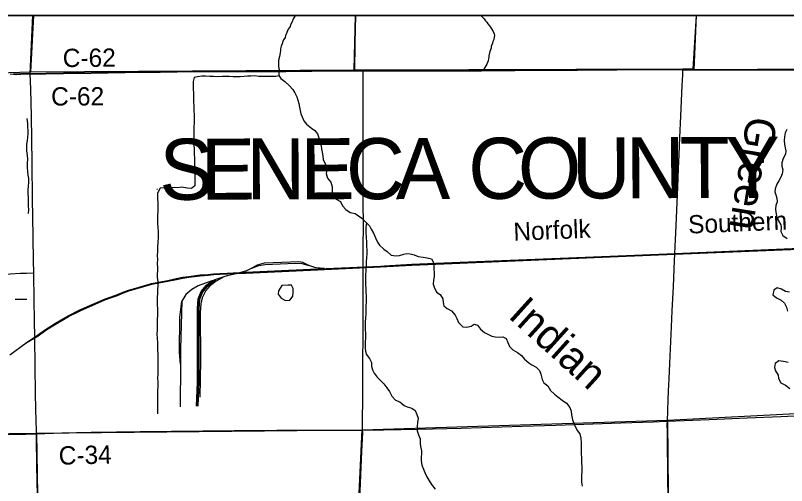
# Model space of a CAD drawing. Extents: x 0 to 34, y 0 to 22.
# Drawn here: x 5.242 to 6.439, y 20.17 to 20.9 of the extents above; entities that cross this region are included whole.
import ezdxf

# ---------------------------------------------------------------- set-up
doc = ezdxf.new("R2010")
doc.units = 0
for name, color, linetype in [('GM_X_Corporation', 7, 'Continuous'), ('GM_X_County_Road', 7, 'Continuous'), ('GM_X_County_Road_Text', 7, 'Continuous'), ('GM_X_County_Text', 7, 'Continuous'), ('GM_X_Minor_Lake', 7, 'Continuous'), ('GM_X_Minor_River', 7, 'Continuous'), ('GM_X_Minor_River_Text', 7, 'Continuous'), ('GM_X_Rail_Line', 7, 'Continuous'), ('GM_X_Rail_Line_Text', 7, 'Continuous'), ('GM_X_Township_Road', 7, 'Continuous'), ('SH_Data', 7, 'Continuous')]:
    doc.layers.add(name, color=color, linetype=linetype)

msp = doc.modelspace()

# ---------------------------------------------------------------- linework, layer by layer
at = {"layer": 'GM_X_Corporation'}
for points in [[(8.9, 20.9), (2.1, 20.9)], [(6.7997, 20.9), (3.8013, 20.9)], [(6.455, 20.8159), (6.4373, 20.816), (6.3938, 20.8159), (6.3543, 20.8158), (6.3344, 20.8158), (6.3036, 20.8158), (6.2954, 20.8159), (6.2828, 20.8161), (6.2781, 20.8161), (6.2682, 20.8162), (6.2104, 20.8162), (6.1757, 20.8159), (6.1145, 20.8155), (6.0613, 20.8151), (6.0172, 20.8146), (5.9656, 20.8142), (5.9482, 20.8141), (5.9187, 20.8141), (5.868, 20.8143), (5.8202, 20.8141), (5.7876, 20.8144), (5.7817, 20.8144), (5.7688, 20.8143), (5.759, 20.8143), (5.7018, 20.8138), (5.6617, 20.8133), (5.6085, 20.8132), (5.5485, 20.8132), (5.5196, 20.8132), (5.4665, 20.8122), (5.4121, 20.8115), (5.3592, 20.8108), (5.3384, 20.8104), (5.3164, 20.8102), (5.289, 20.8097), (5.2645, 20.8094), (5.2558, 20.8096), (5.2527, 20.8095), (5.2501, 20.8093), (5.2468, 20.809), (5.2444, 20.8088), (5.2425, 20.8087), (5.239, 20.8089)], [(5.239, 20.8089), (5.2425, 20.8087), (5.2444, 20.8088), (5.2468, 20.809), (5.2501, 20.8093), (5.2527, 20.8095), (5.2558, 20.8096), (5.2645, 20.8094), (5.289, 20.8097), (5.3164, 20.8102), (5.3384, 20.8104), (5.3592, 20.8108), (5.4121, 20.8115), (5.4665, 20.8122), (5.5196, 20.8132), (5.5485, 20.8132), (5.6085, 20.8132), (5.6617, 20.8133), (5.7018, 20.8138), (5.759, 20.8143), (5.7688, 20.8143), (5.7817, 20.8144), (5.7876, 20.8144), (5.8202, 20.8141), (5.868, 20.8143), (5.9187, 20.8141), (5.9482, 20.8141), (5.9656, 20.8142), (6.0172, 20.8146), (6.0613, 20.8151), (6.1145, 20.8155), (6.1757, 20.8159), (6.2104, 20.8162), (6.2682, 20.8162), (6.2781, 20.8161), (6.2828, 20.8161), (6.2954, 20.8159), (6.3036, 20.8158), (6.3344, 20.8158), (6.3543, 20.8158), (6.3938, 20.8159), (6.4373, 20.816), (6.455, 20.8159)], [(5.239, 20.8089), (5.2425, 20.8087), (5.2444, 20.8088), (5.2468, 20.809), (5.2501, 20.8093), (5.2527, 20.8095), (5.2558, 20.8096), (5.2645, 20.8094), (5.289, 20.8097), (5.3164, 20.8102), (5.3384, 20.8104), (5.3592, 20.8108), (5.4121, 20.8115), (5.4665, 20.8122), (5.5196, 20.8132), (5.5485, 20.8132), (5.6085, 20.8132), (5.6617, 20.8133), (5.7018, 20.8138), (5.759, 20.8143), (5.7688, 20.8143), (5.7817, 20.8144), (5.7876, 20.8144), (5.8202, 20.8141), (5.868, 20.8143), (5.9187, 20.8141), (5.9482, 20.8141), (5.9656, 20.8142), (6.0172, 20.8146), (6.0613, 20.8151), (6.1145, 20.8155), (6.1757, 20.8159), (6.2104, 20.8162), (6.2682, 20.8162), (6.2781, 20.8161), (6.2828, 20.8161), (6.2954, 20.8159), (6.3036, 20.8158), (6.3344, 20.8158), (6.3543, 20.8158), (6.3938, 20.8159), (6.4373, 20.816), (6.455, 20.8159)], [(5.239, 20.8089), (5.2425, 20.8087), (5.2444, 20.8088), (5.2468, 20.809), (5.2501, 20.8093), (5.2527, 20.8095), (5.2558, 20.8096), (5.2645, 20.8094), (5.289, 20.8097), (5.3164, 20.8102), (5.3384, 20.8104), (5.3592, 20.8108), (5.4121, 20.8115), (5.4665, 20.8122), (5.5196, 20.8132), (5.5485, 20.8132), (5.6085, 20.8132), (5.6617, 20.8133), (5.7018, 20.8138), (5.759, 20.8143), (5.7688, 20.8143), (5.7817, 20.8144), (5.7876, 20.8144), (5.8202, 20.8141), (5.868, 20.8143), (5.9187, 20.8141), (5.9482, 20.8141), (5.9656, 20.8142), (6.0172, 20.8146), (6.0613, 20.8151), (6.1145, 20.8155), (6.1757, 20.8159), (6.2104, 20.8162), (6.2682, 20.8162), (6.2781, 20.8161), (6.2828, 20.8161), (6.2954, 20.8159), (6.3036, 20.8158), (6.3344, 20.8158), (6.3543, 20.8158), (6.3938, 20.8159), (6.4373, 20.816), (6.455, 20.8159)]]:
    msp.add_lwpolyline(points, dxfattribs=at)
for points in [[(5.2699, 20.9), (4.8122, 20.9), (4.8145, 20.7984), (5.265, 20.8123)], [(5.7697, 20.9), (5.2699, 20.9), (5.265, 20.8123), (5.7676, 20.8153)], [(6.299, 20.9), (5.7697, 20.9), (5.7676, 20.8153), (5.7804, 20.8154), (6.2773, 20.817), (6.2943, 20.817)], [(6.254, 20.2716), (6.7719, 20.2989), (6.7597, 19.805), (6.7595, 19.7972), (6.2587, 19.7668)], [(5.7802, 20.2569), (6.254, 20.2716), (6.2587, 19.7668), (5.7563, 19.7534)], [(5.2745, 20.2518), (5.2825, 19.7741), (5.2855, 19.7694), (5.2893, 19.764), (5.2986, 19.7516), (5.3057, 19.7445), (5.3092, 19.7364), (4.8186, 19.7484), (4.8123, 20.246)], [(5.2745, 20.2518), (5.7802, 20.2569), (5.7563, 19.7534), (5.2986, 19.7516), (5.2893, 19.764), (5.2855, 19.7694), (5.2825, 19.7741)]]:
    msp.add_lwpolyline(points, close=True, dxfattribs=at)
at = {"layer": 'GM_X_County_Road'}
for p, q in [((5.2646, 20.8092), (5.2691, 20.9)), ((6.2955, 20.8157), (6.2992, 20.9)), ((5.7689, 20.8141), (5.7818, 20.8141))]:
    msp.add_line(p, q, dxfattribs=at)
for points in [[(5.2646, 20.8092), (5.2891, 20.8094), (5.3165, 20.8099), (5.3385, 20.8102), (5.3594, 20.8105), (5.4122, 20.8112), (5.4666, 20.8119), (5.5197, 20.8129), (5.5486, 20.8129), (5.6086, 20.8129), (5.6618, 20.8131), (5.7019, 20.8136), (5.7591, 20.8141), (5.7689, 20.8141)], [(5.2704, 20.5006), (5.2701, 20.5197), (5.2695, 20.5555), (5.269, 20.5881), (5.2686, 20.6145), (5.2679, 20.6714), (5.2673, 20.7078), (5.2667, 20.7438), (5.2656, 20.7855), (5.2646, 20.8092)], [(5.7818, 20.8141), (5.7877, 20.8141), (5.8203, 20.8139), (5.8681, 20.814), (5.9188, 20.8138), (5.9483, 20.8138), (5.9657, 20.8139), (6.0173, 20.8143), (6.0614, 20.8148), (6.1146, 20.8152), (6.1758, 20.8157), (6.2105, 20.8159), (6.2683, 20.8159), (6.2782, 20.8158)], [(6.2782, 20.8158), (6.2829, 20.8158), (6.2955, 20.8157)], [(6.2955, 20.8157), (6.3038, 20.8155), (6.3345, 20.8155), (6.3544, 20.8156), (6.3939, 20.8156), (6.4374, 20.8157), (6.4551, 20.8156), (6.498, 20.8156), (6.5114, 20.8156), (6.5375, 20.8155)], [(5.2744, 20.2508), (5.2744, 20.2553), (5.2737, 20.2882), (5.2732, 20.314), (5.2725, 20.3544), (5.2718, 20.401), (5.2713, 20.4253), (5.271, 20.4595), (5.2705, 20.4977), (5.2704, 20.5006)], [(6.2541, 20.2703), (6.3187, 20.2728), (6.378, 20.2752), (6.4302, 20.2774), (6.4857, 20.2799), (6.5197, 20.2816)], [(5.7809, 20.2564), (5.8138, 20.2567), (5.8673, 20.2578), (5.9341, 20.2595), (6.0286, 20.2624), (6.0811, 20.2642), (6.1817, 20.2676), (6.2327, 20.2693), (6.2513, 20.2702), (6.2541, 20.2703)], [(5.1981, 20.2489), (5.2578, 20.2502), (5.2699, 20.2506), (5.2744, 20.2508)], [(5.2744, 20.2508), (5.3138, 20.252), (5.3595, 20.253), (5.399, 20.2538), (5.4356, 20.2544), (5.4844, 20.2548), (5.5814, 20.2557), (5.6479, 20.2562), (5.7166, 20.2564), (5.7601, 20.2564), (5.7809, 20.2564)], [(5.2798, 19.9976), (5.2798, 19.9993), (5.2795, 20.0104), (5.2787, 20.0381), (5.2772, 20.103), (5.2767, 20.1239), (5.276, 20.1546), (5.2756, 20.1782), (5.2752, 20.2012), (5.2751, 20.2127), (5.2747, 20.2314), (5.2745, 20.2457), (5.2744, 20.2508)]]:
    msp.add_lwpolyline(points, dxfattribs=at)
at = {"layer": 'GM_X_Minor_Lake'}
for points in [[(5.6554, 20.481), (5.6501, 20.4723), (5.6498, 20.4674), (5.6543, 20.4609), (5.6611, 20.4575), (5.6678, 20.4582), (5.6698, 20.4607)], [(5.6698, 20.4607), (5.6727, 20.4642), (5.6729, 20.4692), (5.673, 20.476), (5.6703, 20.4811), (5.6652, 20.4814), (5.6554, 20.481)]]:
    msp.add_lwpolyline(points, dxfattribs=at)
at = {"layer": 'GM_X_Minor_River'}
msp.add_line((5.4624, 20.6297), (5.4615, 20.6299), dxfattribs=at)
for points in [[(5.6766, 20.9), (5.6754, 20.8986), (5.6739, 20.8963), (5.6727, 20.8939), (5.6718, 20.8916), (5.6708, 20.8891), (5.6689, 20.8856), (5.6682, 20.8827), (5.6655, 20.8786), (5.6644, 20.8763), (5.6632, 20.8737), (5.662, 20.8708), (5.6611, 20.8686), (5.6605, 20.8659), (5.6582, 20.8623), (5.657, 20.8595), (5.6558, 20.8559), (5.6544, 20.8521), (5.6536, 20.8481), (5.6534, 20.8457), (5.6528, 20.8424), (5.6524, 20.839), (5.652, 20.836), (5.651, 20.8326), (5.6504, 20.8292), (5.6503, 20.8258), (5.6501, 20.8212), (5.6506, 20.8174), (5.6521, 20.8131)], [(5.9654, 20.9), (5.9656, 20.8991), (5.9694, 20.8947), (5.9716, 20.8918), (5.9739, 20.8895), (5.9755, 20.887), (5.9778, 20.884), (5.9793, 20.8817), (5.9811, 20.879), (5.9838, 20.875), (5.9852, 20.8715), (5.9858, 20.8691), (5.9852, 20.866), (5.9844, 20.8628), (5.9832, 20.8596), (5.9824, 20.857), (5.9816, 20.8541), (5.9806, 20.8519), (5.9802, 20.8492), (5.9794, 20.8464), (5.9785, 20.8441), (5.9767, 20.8373), (5.9767, 20.835), (5.9764, 20.8327), (5.9757, 20.8295), (5.9749, 20.8269), (5.9737, 20.8244), (5.9676, 20.8142)], [(5.6509, 20.813), (5.651, 20.8069), (5.6538, 20.8021), (5.66, 20.7972), (5.6672, 20.7909), (5.6726, 20.7848), (5.6756, 20.7798), (5.6788, 20.7734), (5.6805, 20.7686), (5.6817, 20.7633), (5.6827, 20.7578), (5.684, 20.7525), (5.6852, 20.7473), (5.6869, 20.7426), (5.6897, 20.7365), (5.6935, 20.7314), (5.7014, 20.7252), (5.7067, 20.7216), (5.7106, 20.7161), (5.7128, 20.71), (5.7147, 20.7047), (5.7165, 20.6977), (5.7173, 20.6927), (5.7182, 20.6876), (5.7191, 20.6819), (5.7196, 20.6766), (5.722, 20.6709), (5.7247, 20.6659), (5.7254, 20.661), (5.7242, 20.6546), (5.7261, 20.6473), (5.7313, 20.6411), (5.7334, 20.6338), (5.7335, 20.6261), (5.7344, 20.6213), (5.7397, 20.6146), (5.7463, 20.611), (5.7496, 20.6047), (5.7547, 20.5988), (5.7615, 20.5942), (5.7692, 20.5927), (5.7796, 20.5852)], [(5.6513, 20.8064), (5.6461, 20.8054), (5.6394, 20.8051), (5.6328, 20.8053), (5.6267, 20.8052), (5.6199, 20.8054), (5.6129, 20.806), (5.6071, 20.8058), (5.602, 20.8057), (5.5968, 20.8051), (5.5906, 20.8048), (5.58, 20.8049), (5.5739, 20.8053), (5.5681, 20.8051), (5.5631, 20.8052), (5.556, 20.8048), (5.5495, 20.8052), (5.5435, 20.8051), (5.5372, 20.8057), (5.531, 20.8055), (5.5243, 20.8048), (5.5194, 20.8035), (5.5177, 20.7973), (5.5176, 20.7918), (5.518, 20.785), (5.5181, 20.7796), (5.5183, 20.7719), (5.5184, 20.7658), (5.5188, 20.7599), (5.5189, 20.7525), (5.5192, 20.7453), (5.5192, 20.7332), (5.5189, 20.7269), (5.5188, 20.7099), (5.5186, 20.7047), (5.5186, 20.6983), (5.5191, 20.6934), (5.5196, 20.686), (5.5197, 20.6767), (5.5199, 20.6713), (5.5199, 20.6657), (5.5202, 20.6592), (5.5202, 20.653), (5.5203, 20.6482), (5.5205, 20.6418), (5.5204, 20.6353), (5.5151, 20.6314), (5.5083, 20.632), (5.5003, 20.6332), (5.4937, 20.6323), (5.4884, 20.6329), (5.4818, 20.6323), (5.4735, 20.6322), (5.4668, 20.632), (5.4626, 20.6239), (5.4626, 20.6159), (5.4627, 20.6093), (5.4631, 20.6046), (5.4628, 20.5983), (5.4626, 20.5872)], [(5.2597, 20.7399), (5.2604, 20.7325), (5.2606, 20.7272), (5.2609, 20.7209), (5.261, 20.716), (5.2608, 20.7109), (5.26, 20.7057), (5.259, 20.7003), (5.259, 20.6946), (5.2591, 20.6898), (5.26, 20.6828), (5.2606, 20.6769), (5.2603, 20.6705), (5.2603, 20.664), (5.2606, 20.6579), (5.2613, 20.6522), (5.262, 20.6467), (5.2624, 20.6405), (5.2618, 20.6355), (5.2611, 20.6289), (5.2611, 20.6238), (5.2616, 20.6171), (5.2618, 20.6101), (5.2617, 20.6039), (5.2619, 20.5989), (5.2616, 20.5928)], [(6.4394, 20.7227), (6.4367, 20.7178), (6.4357, 20.7115), (6.4355, 20.7058), (6.436, 20.7003), (6.4367, 20.6946), (6.4377, 20.6899), (6.4372, 20.6849), (6.4338, 20.6778), (6.4317, 20.6711), (6.4316, 20.6658), (6.4331, 20.6605), (6.4323, 20.6543), (6.43, 20.649), (6.4271, 20.6435), (6.4241, 20.6382), (6.4212, 20.6308), (6.4208, 20.6261), (6.4223, 20.6213), (6.4241, 20.6162), (6.4243, 20.6105), (6.4225, 20.6048), (6.4221, 20.5991), (6.4223, 20.5944), (6.4232, 20.5891), (6.4264, 20.5813)], [(5.4626, 20.5872), (5.4624, 20.5773), (5.4631, 20.5703), (5.4637, 20.5652), (5.4637, 20.5598), (5.4634, 20.5551), (5.4628, 20.5483), (5.4624, 20.5405), (5.4622, 20.5341), (5.4621, 20.5269), (5.4623, 20.5215), (5.4621, 20.5147), (5.4622, 20.509), (5.4621, 20.4935), (5.4629, 20.4867), (5.4628, 20.4808), (5.4624, 20.4739), (5.4622, 20.4686), (5.4621, 20.4628), (5.4617, 20.4567), (5.4619, 20.4502), (5.4622, 20.4453), (5.4621, 20.4176), (5.4619, 20.4119), (5.4616, 20.4051), (5.462, 20.3989), (5.4623, 20.3918), (5.4624, 20.3844), (5.4626, 20.3797), (5.4628, 20.3742), (5.4627, 20.3615), (5.463, 20.3556), (5.463, 20.349), (5.4628, 20.3437), (5.4626, 20.3367), (5.4627, 20.3312), (5.4629, 20.3241), (5.4626, 20.3179), (5.4624, 20.3131), (5.4624, 20.3063), (5.4623, 20.2999), (5.4623, 20.2866), (5.4626, 20.2818)], [(5.7796, 20.5852), (5.7865, 20.5787), (5.7918, 20.5732), (5.794, 20.5684), (5.7977, 20.5618), (5.8009, 20.5546), (5.8041, 20.5483), (5.8071, 20.5435), (5.8137, 20.5372), (5.819, 20.5336), (5.8252, 20.5281), (5.8324, 20.5267), (5.8382, 20.5276), (5.8447, 20.5293), (5.8496, 20.5304), (5.8545, 20.5302), (5.8607, 20.5282), (5.8673, 20.5257), (5.8749, 20.5246), (5.8813, 20.5236), (5.8879, 20.5224), (5.8907, 20.5165), (5.8913, 20.5118), (5.8914, 20.507), (5.8922, 20.5002), (5.8918, 20.4949), (5.891, 20.489), (5.8902, 20.4829), (5.8918, 20.478), (5.8956, 20.4704), (5.9012, 20.4671), (5.9056, 20.4599), (5.9061, 20.4546), (5.907, 20.4495), (5.9123, 20.4453), (5.9191, 20.4416), (5.9247, 20.435), (5.9269, 20.4298), (5.9299, 20.4232), (5.9365, 20.4167), (5.9429, 20.4159), (5.9496, 20.4176), (5.9543, 20.4206), (5.9592, 20.4192), (5.9641, 20.4133), (5.9701, 20.4078), (5.9754, 20.4055), (5.9816, 20.402), (5.9869, 20.4009), (5.9934, 20.4008), (5.9985, 20.401), (6.0039, 20.3985), (6.0064, 20.3926), (6.009, 20.3859), (6.0142, 20.381), (6.0212, 20.3766), (6.0273, 20.3724), (6.0323, 20.3665), (6.0389, 20.3607), (6.0438, 20.3577), (6.0504, 20.3542), (6.0555, 20.3487), (6.0577, 20.343), (6.0596, 20.3347), (6.0624, 20.3299), (6.0686, 20.3249), (6.0727, 20.3181), (6.0787, 20.3122), (6.0838, 20.308), (6.0908, 20.3028), (6.0974, 20.2984), (6.1028, 20.2916), (6.1045, 20.286), (6.1054, 20.28), (6.1067, 20.2724), (6.1087, 20.2671), (6.1112, 20.2608), (6.1145, 20.2555), (6.1179, 20.2505), (6.1196, 20.2439), (6.1203, 20.2366), (6.1201, 20.2302), (6.12, 20.2249), (6.1202, 20.2198), (6.1207, 20.2131), (6.1205, 20.2069), (6.1212, 20.1981), (6.121, 20.1919), (6.1208, 20.1853), (6.1207, 20.1805), (6.1209, 20.1756), (6.1218, 20.1695)], [(6.4264, 20.5813), (6.4302, 20.5749), (6.4308, 20.5702), (6.4304, 20.5647), (6.4334, 20.5584), (6.4398, 20.5538)], [(5.7877, 20.5774), (5.7863, 20.5761), (5.7857, 20.5698), (5.786, 20.562), (5.7866, 20.5567), (5.7869, 20.5465), (5.787, 20.5415), (5.7872, 20.536), (5.7872, 20.5309), (5.7869, 20.5237), (5.7865, 20.5182), (5.7863, 20.5135), (5.7859, 20.5078), (5.7857, 20.5029), (5.7856, 20.4977), (5.7854, 20.493), (5.7852, 20.4879), (5.7854, 20.4824), (5.7859, 20.4756), (5.7861, 20.4702), (5.7862, 20.4646), (5.7864, 20.4594), (5.7862, 20.4547), (5.7859, 20.4498), (5.7857, 20.4441), (5.7857, 20.4374), (5.7853, 20.4301), (5.7848, 20.4246), (5.7848, 20.4194), (5.785, 20.4126), (5.7851, 20.4065), (5.7853, 20.4001), (5.785, 20.3931), (5.785, 20.3836), (5.7851, 20.3788), (5.7866, 20.3741), (5.7917, 20.3676), (5.7945, 20.3614), (5.7947, 20.3557), (5.796, 20.35), (5.7986, 20.3446), (5.8036, 20.3385), (5.8082, 20.3338), (5.8138, 20.3284), (5.8183, 20.3218), (5.8226, 20.3161), (5.8264, 20.309), (5.832, 20.3029), (5.8388, 20.3004), (5.8452, 20.2945), (5.8501, 20.2926), (5.8571, 20.2903), (5.8626, 20.287), (5.8652, 20.2806), (5.867, 20.2749), (5.8662, 20.2684), (5.8656, 20.2622), (5.8658, 20.2555), (5.8676, 20.2491), (5.8701, 20.243), (5.8702, 20.2358), (5.8709, 20.231), (5.8722, 20.2242), (5.8722, 20.2193), (5.8718, 20.2143), (5.8716, 20.209), (5.8727, 20.202), (5.8753, 20.1957), (5.8777, 20.1906), (5.8805, 20.1841), (5.8835, 20.1788), (5.8878, 20.1718), (5.8936, 20.1645)], [(6.4436, 20.4707), (6.4376, 20.4717), (6.431, 20.4752), (6.4246, 20.4771), (6.4191, 20.4737), (6.4177, 20.4665), (6.4233, 20.4616), (6.4309, 20.4581), (6.4358, 20.4535), (6.4389, 20.4473), (6.4404, 20.4412)], [(5.2413, 20.4597), (5.2485, 20.4597), (5.2548, 20.4594), (5.2597, 20.4598)], [(6.4413, 20.3612), (6.4345, 20.3627), (6.4273, 20.3639), (6.4214, 20.3599), (6.4202, 20.3533), (6.4219, 20.3484), (6.4259, 20.3417), (6.4268, 20.3364), (6.4301, 20.3297), (6.4373, 20.3261), (6.4439, 20.3211)]]:
    msp.add_lwpolyline(points, dxfattribs=at)
at = {"layer": 'GM_X_Rail_Line'}
for p, q in [((5.5532, 20.4901), (5.5501, 20.4891)), ((5.5655, 20.4941), (5.5532, 20.4901)), ((5.4979, 20.3588), (5.4975, 20.2925))]:
    msp.add_line(p, q, dxfattribs=at)
for points in [[(5.2331, 20.3734), (5.2586, 20.3917), (5.277, 20.4029), (5.2893, 20.4115), (5.2975, 20.4168), (5.3049, 20.4211), (5.3137, 20.4263), (5.3245, 20.4328), (5.3422, 20.4417), (5.3805, 20.4585), (5.3909, 20.4622), (5.4005, 20.4655), (5.4098, 20.4694), (5.418, 20.4723), (5.429, 20.4757), (5.4535, 20.4827), (5.4643, 20.4848), (5.4786, 20.4876), (5.4917, 20.4903), (5.5017, 20.4923), (5.5111, 20.4936), (5.5289, 20.496), (5.5413, 20.4969), (5.5497, 20.4977), (5.5592, 20.4982), (5.5709, 20.499), (5.5994, 20.5002), (5.7, 20.5047), (5.8089, 20.5096), (5.8572, 20.5125), (5.9195, 20.5151), (6.1652, 20.5252), (6.2654, 20.5295), (6.4841, 20.5385)], [(5.2572, 20.3906), (5.2763, 20.4039), (5.2886, 20.4126), (5.2969, 20.4179), (5.3043, 20.4222), (5.3131, 20.4274), (5.3239, 20.4339), (5.3417, 20.4429), (5.3801, 20.4597), (5.3905, 20.4634), (5.4001, 20.4667), (5.4093, 20.4705), (5.4176, 20.4734), (5.4287, 20.4769), (5.4532, 20.4839), (5.464, 20.486), (5.4783, 20.4888), (5.4915, 20.4915), (5.5015, 20.4935), (5.5109, 20.4949), (5.5287, 20.4972), (5.5412, 20.4981), (5.5496, 20.499), (5.5591, 20.4995), (5.5708, 20.5002), (5.5993, 20.5014), (5.7, 20.506), (5.8088, 20.5108), (5.8149, 20.5112), (5.8571, 20.5137), (5.9194, 20.5163), (6.1652, 20.5265), (6.2654, 20.5307), (6.4841, 20.5397)], [(5.6975, 20.5121), (5.6882, 20.5165), (5.6816, 20.5173), (5.6557, 20.5166), (5.6278, 20.5154), (5.6171, 20.5125), (5.6088, 20.5079)], [(5.6088, 20.5079), (5.6197, 20.5118), (5.6297, 20.5134), (5.6761, 20.5155), (5.6867, 20.515), (5.6975, 20.5121)], [(5.7218, 20.507), (5.7084, 20.508), (5.6975, 20.5121)], [(5.5894, 20.4998), (5.5707, 20.4957), (5.5655, 20.4941)], [(5.6088, 20.5079), (5.6068, 20.5067), (5.6004, 20.5034), (5.5918, 20.5011)], [(5.5468, 20.488), (5.5258, 20.4805), (5.5155, 20.4748), (5.5064, 20.4668), (5.5001, 20.4564)], [(5.5231, 20.2934), (5.5245, 20.3308), (5.5247, 20.4083), (5.5244, 20.4449), (5.5258, 20.4602), (5.5301, 20.4715), (5.5386, 20.4811), (5.5468, 20.488)], [(5.5243, 20.2934), (5.5258, 20.3307), (5.5259, 20.4083), (5.5257, 20.4449), (5.527, 20.46), (5.5312, 20.4708), (5.5395, 20.4802), (5.5476, 20.487), (5.5501, 20.4891)], [(5.5256, 20.2933), (5.527, 20.3307), (5.5272, 20.4083), (5.5269, 20.4448), (5.5282, 20.4597), (5.5323, 20.4701), (5.5403, 20.4793), (5.5484, 20.4861), (5.5532, 20.4901)], [(5.5655, 20.4941), (5.5536, 20.4877), (5.5445, 20.4809), (5.5371, 20.4722), (5.5319, 20.4618), (5.5295, 20.4525), (5.5286, 20.4391), (5.5294, 20.3646), (5.528, 20.3073)], [(5.5501, 20.4891), (5.5492, 20.4888), (5.5468, 20.488)], [(5.4979, 20.3588), (5.4964, 20.3766), (5.4972, 20.4319), (5.5001, 20.4564)], [(5.5001, 20.4564), (5.498, 20.3827), (5.4979, 20.3588)]]:
    msp.add_lwpolyline(points, dxfattribs=at)
at = {"layer": 'GM_X_Township_Road'}
msp.add_line((5.7689, 20.8141), (5.7699, 20.9), dxfattribs=at)
for points in [[(5.2339, 20.8091), (5.2391, 20.8086), (5.2426, 20.8084), (5.2431, 20.8085)], [(5.2431, 20.8085), (5.2445, 20.8086), (5.2469, 20.8087), (5.2502, 20.809), (5.2528, 20.8092), (5.2559, 20.8093), (5.2646, 20.8092)], [(5.7809, 20.2564), (5.7808, 20.2603), (5.7809, 20.2693), (5.781, 20.3069), (5.7812, 20.342), (5.7819, 20.4241), (5.7819, 20.4978), (5.7818, 20.5279), (5.782, 20.5864), (5.7818, 20.5982), (5.7816, 20.6796), (5.7815, 20.7032), (5.7816, 20.7433), (5.7817, 20.7822), (5.7818, 20.8141)], [(6.2655, 20.5293), (6.266, 20.542), (6.2669, 20.5622), (6.2685, 20.5979), (6.2701, 20.6333), (6.2713, 20.6625), (6.2722, 20.6839), (6.2734, 20.7103), (6.2749, 20.7439), (6.2761, 20.7675), (6.2771, 20.7914), (6.2779, 20.8078), (6.2782, 20.8158)], [(6.2541, 20.2703), (6.2554, 20.3036), (6.256, 20.3172), (6.2569, 20.3359), (6.2579, 20.3595), (6.2605, 20.4166), (6.2616, 20.4415), (6.262, 20.4511), (6.2633, 20.4787), (6.2651, 20.5197), (6.2655, 20.5293)], [(5.1211, 20.4957), (5.1271, 20.4959), (5.1349, 20.4962), (5.1448, 20.4965), (5.1524, 20.4967), (5.1667, 20.497), (5.1859, 20.4975), (5.2039, 20.498), (5.2189, 20.4985), (5.2338, 20.499), (5.2498, 20.4998), (5.2592, 20.5002), (5.2692, 20.5005), (5.2704, 20.5006)], [(6.26, 19.7668), (6.2601, 19.769), (6.2603, 19.7709), (6.2604, 19.774), (6.2603, 19.7849), (6.26, 19.8089), (6.2594, 19.8567), (6.2584, 19.9021), (6.2576, 19.9419), (6.2572, 19.9739), (6.2567, 19.9997), (6.2562, 20.0261), (6.2561, 20.0413), (6.2554, 20.0976), (6.255, 20.1454), (6.2547, 20.1893), (6.2542, 20.2387), (6.254, 20.2545), (6.2539, 20.2645), (6.2541, 20.2703)], [(5.7738, 20.0667), (5.774, 20.0705), (5.7753, 20.1102), (5.7773, 20.1621), (5.7799, 20.2233), (5.781, 20.2528), (5.7809, 20.2564)]]:
    msp.add_lwpolyline(points, dxfattribs=at)
at = {"layer": 'SH_Data'}
msp.add_line((2.1, 20.9), (8.9, 20.9), dxfattribs=at)

# ---------------------------------------------------------------- texts
at = {"layer": 'GM_X_County_Road_Text'}
for s, rotation, p in [('C-62', 0.391, (5.3154, 20.8198)), ('C-62', 0.1228, (5.2973, 20.7601)), ('C-34', 1.3559, (5.3094, 20.2026))]:
    msp.add_text(s, height=0.02841, rotation=rotation, dxfattribs=at).set_placement(p)
at = {"layer": 'GM_X_County_Text'}
for s, rotation, p in [('S', 0.2328, (5.4655, 20.6137)), ('E', 0.2359, (5.5297, 20.614)), ('N', 0.2284, (5.6005, 20.6143)), ('E', 0.1826, (5.6842, 20.6146)), ('C', 359.9646, (5.755, 20.6149)), ('A', 0.1953, (5.8325, 20.6148)), ('C', 0.2167, (5.945, 20.6152)), ('O', 0.2175, (6.0221, 20.6155)), ('U', 0.2191, (6.1059, 20.6158)), ('N', 0.2197, (6.1896, 20.6161)), ('T', 0.2201, (6.2734, 20.6165)), ('Y', 0.2197, (6.3442, 20.6167))]:
    msp.add_text(s, height=0.0947, rotation=rotation, dxfattribs=at).set_placement(p)
at = {"layer": 'GM_X_Minor_River_Text'}
for s, height, rotation, p in [('Green', 0.04738, 260.8718, (6.378, 20.745)), ('Indian', 0.04737, 317.8779, (6.0053, 20.4321))]:
    msp.add_text(s, height=height, rotation=rotation, dxfattribs=at).set_placement(p)
at = {"layer": 'GM_X_Rail_Line_Text'}
for s, rotation, p in [('Southern', 2.4279, (6.2869, 20.5613)), ('Norfolk', 2.4406, (6.0156, 20.55))]:
    msp.add_text(s, height=0.02831, rotation=rotation, dxfattribs=at).set_placement(p)

doc.saveas('drawing.dxf')
